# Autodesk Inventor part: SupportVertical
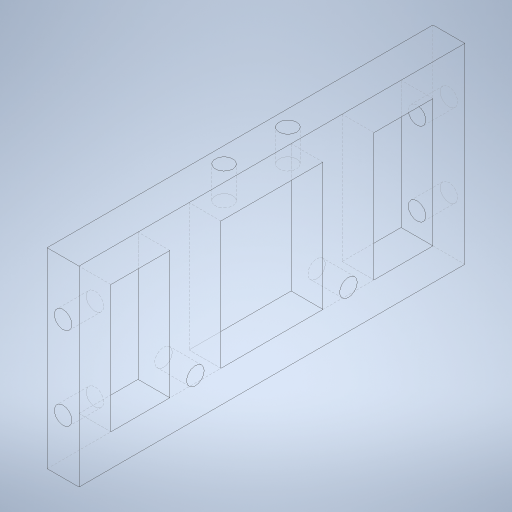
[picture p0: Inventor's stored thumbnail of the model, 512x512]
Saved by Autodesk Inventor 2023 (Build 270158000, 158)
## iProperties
Created: 2023-10
Part Number: SupportVertical
Material: Aluminum 7075
Document SubType Name: Modeling
Designer: tornqvih
Density: 2.81 g/cm^3
Appearance: Satin - Brushed Heavy
Mass: 139.831 g
Surface Area: 196.874 cm^2
Volume: 49.7618 cm^3
Author: tornqvih
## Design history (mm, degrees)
sketch "Sketch1"
  geometry: L1 (-30, 60.5)-(30, 60.5); L2 (30, 60.5)-(30, -60.5); L3 (30, -60.5)-(-30, -60.5); L4 (-30, -60.5)-(-30, 60.5); L5 (-30, 60.5)-(30, -60.5); L6 (30, 60.5)-(-30, -60.5); 1 further point
  constraints: 12 end point, 2 midpoint, 2 parallel, 1 horizontal, 1 perpendicular
  dimensions: "d0" = 121 distance of L1.end L2.end; "d1" = 60 distance of L1.start L1.end
extrude "Extrusion1" new body sketch "Sketch1" distance "d2" = 10; taper "d3" = 0 deg
sketch "Sketch2"
  geometry: L1 (-50.5, 20)-(-32, 20); L2 (-32, 20)-(-32, -20); L3 (-32, -20)-(-50.5, -20); L4 (-50.5, -20)-(-50.5, 20); L5 (32, 20)-(50.5, 20); L6 (50.5, 20)-(50.5, -20); L7 (50.5, -20)-(32, -20); L8 (32, -20)-(32, 20); L9 (0, -42)-(0, 42) reference; L10 (84.7, 0)-(-84.7, 0) reference; L11 (60.5, 30)-(-60.5, 30) reference; L12 (-60.5, 30)-(-60.5, -30) reference; L13 (-16, 20)-(16, 20); L14 (16, 20)-(16, -20); L15 (16, -20)-(-16, -20); L16 (-16, -20)-(-16, 20); L17 (-60.5, -30)-(60.5, -30) reference; 1 further point
  constraints: 24 end point, 6 parallel, 5 symmetric about line, 3 horizontal, 3 perpendicular, 2 horizontal alignment, 2 point on line
  dimensions: "d4" = 10 distance between parallel lines of L11 L1; "d5" = 10 distance between parallel lines of L12 L4; "d11" = 16 distance between parallel lines of L9 L16; "d42" = 16 distance between parallel lines of L16 L2; "d52" = 10 distance between parallel lines of L17 L3
extrude "Extrusion2" cut sketch "Sketch2" distance "d9" = 10; taper "d10" = 0 deg
sketch "Sketch3"
  geometry: L1 (0, 60)-(0, 0) reference; L2 (0, 60)-(10, 60) reference; L3 (0, 0)-(10, 0) reference; 3 further points
  constraints: 1 vertical alignment
  dimensions: "d12" = 5 distance from line of L1 point (5, 43); "d13" = 17 distance from line of L2 point (5, 43); "d14" = 17 distance from line of L3 point (5, 17)
hole "Hole1" sketch "Sketch3" at (5, 43), (5, 17) diameter "d15" = 5.5; stored, may be unused: countersink angle "d19" = 90 deg, drill point angle "d21" = 118 deg; dims "d16" = 6, "d17" = 4, "d18" = 2, "d20" = 10
sketch "Sketch4"
  geometry: 4 further points
  constraints: 2 coincident
hole "Hole2" sketch "Sketch4" at (-5, 43), (-5, 17) diameter "d25" = 5.5; stored, may be unused: countersink angle "d29" = 90 deg, drill point angle "d31" = 118 deg; dims "d26" = 6, "d27" = 4, "d28" = 2, "d30" = 10
sketch "Sketch5"
  geometry: L1 (0, 121)-(0, 0) reference; 5 further points
  constraints: 2 vertical alignment, 1 horizontal alignment, 1 midpoint
  dimensions: "d32" = 5 distance from line of L1 point (5, 60.5); "d33" = 10 distance of point (5, 50.5) point (5, 60.5); "d34" = 10 distance of point (5, 70.5) point (5, 60.5)
hole "Hole3" sketch "Sketch5" at (5, 50.5), (5, 70.5) diameter "d35" = 5.5; stored, may be unused: countersink angle "d39" = 90 deg, drill point angle "d41" = 118 deg; dims "d36" = 6, "d37" = 4, "d38" = 2, "d40" = 10
sketch "Sketch6"
  geometry: L1 (0, -42)-(0, 42) reference; L2 (-60.5, -30)-(60.5, -30) reference; L3 (-16, -20)-(-16, 20) reference; 3 further points
  constraints: 1 symmetric about line
  dimensions: "d44" = 12 distance from line of L2 point (-24, -18); "d53" = 8 distance from line of L3 point (-24, -18)
hole "Hole4" sketch "Sketch6" at (-24, -18), (24, -18) diameter "d45" = 5.5; stored, may be unused: countersink angle "d49" = 90 deg, drill point angle "d51" = 118 deg; dims "d46" = 6, "d47" = 4, "d48" = 2, "d50" = 10
body "Solid1"
